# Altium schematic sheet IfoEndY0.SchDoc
size C; Engineer: Daniel Sigg; DocumentNumber: 4; SheetNumber: 28; SheetTotal: 33
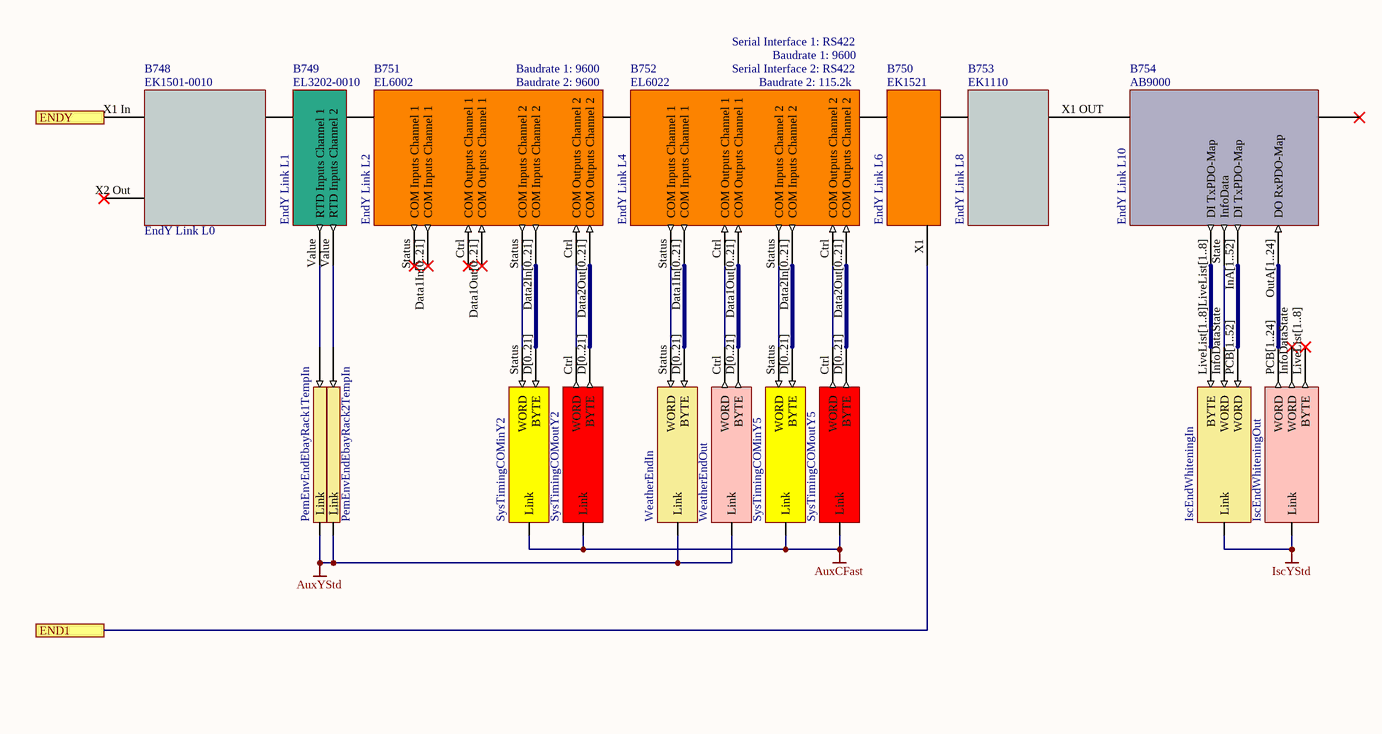
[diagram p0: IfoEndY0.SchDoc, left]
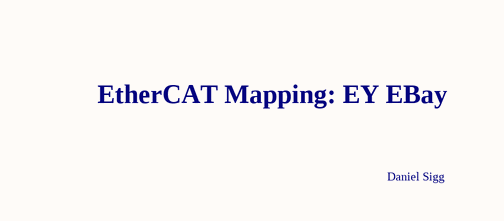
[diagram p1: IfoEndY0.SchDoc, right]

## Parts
B748  EndY Link L0  Part Number: EK1501-0010  (mechanical)
B749  EndY Link L1  Part Number: EL3202-0010  (mechanical)
B750  EndY Link L6  Part Number: EK1521  (mechanical)
B751  EndY Link L2  Part Number: EL6002  Baudrate 1: 9600  (mechanical)
B752  EndY Link L4  Part Number: EL6022  Baudrate 1: 9600  Baudrate 2: 115.2k  Serial Interface 1: RS422  (mechanical)
B753  EndY Link L8  Part Number: EK1110  (mechanical)
B754  EndY Link L10  Part Number: AB9000  (mechanical)
V618  PemEnvEndEbayRack1TempIn  (no BOM)
V619  PemEnvEndEbayRack2TempIn  (no BOM)
V620  IscEndWhiteningIn  (no BOM)
V621  IscEndWhiteningOut  (no BOM)
V622  SysTimingCOMinY2  (no BOM)
V623  SysTimingCOMoutY2  (no BOM)
V624  SysTimingCOMinY5  (no BOM)
V625  SysTimingCOMoutY5  (no BOM)
V847  WeatherEndIn  (no BOM)
V848  WeatherEndOut  (no BOM)

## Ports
END1, ENDY

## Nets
AuxCFast: V622.?1(Link) V623.?1(Link) V624.?1(Link) V625.?1(Link)
AuxYStd: V618.?2(Link) V619.?2(Link) V847.?1(Link) V848.?1(Link)
IscYStd: V620.?1(Link) V621.?1(Link)
END1: B750.X1(D) ; port END1
ENDY: B748.X1_In(A) ; port ENDY
NetB748_Ebus: B748.Ebus(B) B749.Ebus(A)
NetB749_Ebus: B749.Ebus(B) B751.Ebus(A)
NetB749_Value: B749.Value(RTD_Inputs_Channel_1) V618.?1
NetB749_Value: B749.Value(RTD_Inputs_Channel_2) V619.?1  [a separate net that carries the same name]
NetB750_Ebus: B750.Ebus(A) B752.Ebus(B)
NetB750_Ebus: B750.Ebus(C) B753.Ebus(A)  [a separate net that carries the same name]
NetB751_Ctrl: B751.Ctrl(COM_Outputs_Channel_1) V623.Ctrl(WORD)
NetB751_Data2In[0..21]: B751.Data2In[0..21](COM_Inputs_Channel_2) V622.D[0..21](BYTE)
NetB751_Data2Out[0..21]: B751.Data2Out[0..21](COM_Outputs_Channel_2) V623.D[0..21](BYTE)
NetB751_Ebus: B751.Ebus(B) B752.Ebus(A)
NetB751_Status: B751.Status(COM_Inputs_Channel_1) V622.Status(WORD)
NetB752_Ctrl: B752.Ctrl(COM_Outputs_Channel_1) V848.Ctrl(WORD)
NetB752_Ctrl: B752.Ctrl(COM_Outputs_Channel_2) V625.Ctrl(WORD)  [a separate net that carries the same name]
NetB752_Data1In[0..21]: B752.Data1In[0..21](COM_Inputs_Channel_1) V847.D[0..21](BYTE)
NetB752_Data1Out[0..21]: B752.Data1Out[0..21](COM_Outputs_Channel_1) V848.D[0..21](BYTE)
NetB752_Data2In[0..21]: B752.Data2In[0..21](COM_Inputs_Channel_2) V624.D[0..21](BYTE)
NetB752_Data2Out[0..21]: B752.Data2Out[0..21](COM_Outputs_Channel_2) V625.D[0..21](BYTE)
NetB752_Status: B752.Status(COM_Inputs_Channel_1) V847.Status(WORD)
NetB752_Status: B752.Status(COM_Inputs_Channel_2) V624.Status(WORD)  [a separate net that carries the same name]
NetB753_X1 OUT: B753.X1_OUT(B) B754.?2(A)
NetB754_InA[1..52]: B754.InA[1..52](DI_TxPDO-Map) V620.PCB[1..52](WORD)
NetB754_LiveList[1..8]: B754.LiveList[1..8](DI_TxPDO-Map) V620.LiveList[1..8](BYTE)
NetB754_OutA[1..24]: B754.OutA[1..24](DO_RxPDO-Map) V621.PCB[1..24](WORD)
NetB754_State: B754.State(InfoData) V620.InfoDataState(WORD)

Not connected (* = marked no-connect by the designer): B748 X2 Out(C)*; B751 Data1In[0..21](COM_Inputs_Channel_1)* Data1Out[0..21](COM_Outputs_Channel_1)*; B754 ?1(B)*; V621 InfoDataState(WORD)* LiveList[1..8](BYTE)*

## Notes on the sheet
- EtherCAT Mapping: EY EBay
- Daniel Sigg

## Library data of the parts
B748 = CouplerEK1501: Fiber Coupler; Rail: Left; BoxNextB: TWDJDPST; BoxPrev: SPLHFTMV; PortPrevFull: 1001/B; PortPrevShort: B 'X1'; Fullname: TIID^End Y (EtherCAT)^EndY Link L0 (EK1501-0010); BoxPorts: Junction; BoxAddr: 1002; Disabled: False
B749 = TerminalEL3202-0010: EtherCAT Terminal EL3202-0010 2-chn Temperature Input; Rail: Left; BoxNextB: UBGJKAPH; BoxPrev: JHYOYQCQ; PortPrevFull: 1002/B; PortPrevShort: B; Fullname: TIID^End Y (EtherCAT)^EndY Link L0 (EK1501-0010)^EndY Link L1 (EL3202-0010); BoxAddr: 1003; Disabled: False
B750 = TerminalEK1521: EtherCAT Terminal Fiber; Rail: Left; BoxNextC: YFMTQQBN; BoxNextD: NEQKDDQF; BoxPrev: PMKJUTTD; PortPrevFull: 1005/B; PortPrevShort: B; Fullname: TIID^End Y (EtherCAT)^EndY Link L0 (EK1501-0010)^EndY Link L6 (EK1521); BoxPorts: Junction; BoxAddr: 1006; Disabled: False
B751 = TerminalEL6002: EtherCAT Terminal EL6002 Dual RS232; Rail: Left; BoxNextB: PMKJUTTD; BoxPrev: TWDJDPST; PortPrevFull: 1003/B; PortPrevShort: B; Fullname: TIID^End Y (EtherCAT)^EndY Link L0 (EK1501-0010)^EndY Link L2 (EL6002); BoxAddr: 1004; BoxSubType: 9101; Disabled: False
B752 = TerminalEL6022: EtherCAT Terminal EL6022 Dual RS422; Rail: Left; BoxNextB: CKQXTAKS; BoxPrev: UBGJKAPH; PortPrevFull: 1004/B; PortPrevShort: B; Fullname: TIID^End Y (EtherCAT)^EndY Link L0 (EK1501-0010)^EndY Link L4 (EL6022); BoxAddr: 1005; BoxSubType: 9103; Disabled: False
B753 = CouplerEK1110: EtherCAT Coupler Extension; BoxType: Terminal; Rail: Left; BoxNextB: KTWIWDVY; BoxPrev: CKQXTAKS; PortPrevFull: 1006/C; PortPrevShort: C; Fullname: TIID^End Y (EtherCAT)^EndY Link L0 (EK1501-0010)^EndY Link L8 (EK1110); BoxAddr: 1126; Disabled: False
B754 = Anybus X-gateway 1xBIO: EtherCAT Modbus gateway for 1xBIO; Part Revision: V0000001b_P0000001b_R0001000d; BoxType: Box; BoxPrev: YFMTQQBN; PortPrevFull: 1126/B; PortPrevShort: B 'X1 OUT'; Fullname: TIID^End Y (EtherCAT)^EndY Link L10 (AB9000); BoxAddr: 1127; PDO Inputs: 0x1A01; PDO Outputs: 0x1601; Disabled: False
V618 V619 = VariableInINT: INT; PLC: H1AuxEndY; Task: AuxEStd; Instance: H1AuxEndY Instance
V620 = ISCWhitening_IscWhiteningInStruct: IscWhiteningInStruct; BoxType: Variable; Instance: H1IscEndY Instance; PLC: H1IscEndY; Task: IscEStd
V621 = ISCWhitening_IscWhiteningOutStruct: IscWhiteningOutStruct; BoxType: Variable; Instance: H1IscEndY Instance; PLC: H1IscEndY; Task: IscEStd
V622 V624 = Serial_EL6inData22Bfast: EL6inData22B; PLC: H1AuxCorner; Task: AuxCFast; BoxType: Variable; Instance: H1AuxCorner Instance
V623 V625 = Serial_EL6outData22Bfast: EL6outData22B; PLC: H1AuxCorner; Task: AuxCFast; BoxType: Variable; Instance: H1AuxCorner Instance
V847 = Serial_EL6inData22B: EL6inData22B; PLC: H1AuxEndY; Task: AuxEStd; BoxType: Variable; Instance: H1AuxEndY Instance
V848 = Serial_EL6outData22B: EL6outData22B; PLC: H1AuxEndY; Task: AuxEStd; BoxType: Variable; Instance: H1AuxEndY Instance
